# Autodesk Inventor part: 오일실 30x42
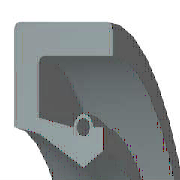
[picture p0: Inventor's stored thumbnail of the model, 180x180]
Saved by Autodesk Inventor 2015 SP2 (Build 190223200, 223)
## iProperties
IsCustomPart: 0
Company: 한국ATC센터
Created: 2009-02
Part Number: 오일실 30x42
Material: 고무
Description: 오일-실
Document SubType Name: Modeling
Standard: KS B 2804
Designer: KYOUNG IL JANG
Standards Organization: KS
Language: ko-KR
Size Designation: S - 30 42 8
Categories: <MemberInstance><Categories><Category DisplayName="샤프트 부품" InternalName="7f7aeb1f-a693-4053-b835-cee3144e0d98" Mnemonic="SHFT"><Category DisplayName="실링" Intern
Density: 0.93 g/cm^3
Appearance: 고무 - 검은색 - 버전 1.1
Author: KYOUNG IL JANG
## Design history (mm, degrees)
revolve "본체" stored, may be unused: angle "d17" = 90 deg
revolve "스프링1" stored, may be unused: angle "d18" = 90 deg
body "Solid1"
sketch "스케치1"
  geometry: L1 (0, 21)-(8, 21); L2 (8, 21)-(8, 19.75); L3 (8, 19.75)-(1.75, 19.75); L4 (0, 21)-(0, 17.1); L5 (0, 17.1)-(1.75, 16.75); L6 (1.75, 16.75)-(4.9, 15); L7 (4.9, 15)-(0, 15); L8 (6.3, 15.875)-(6.3, 17.1); L9 (0, 0)-(9.586, 0) reference; L10 (4.9, 15)-(6.3, 15.875); L11 (0, 18)-(0, -3) reference; L12 (-1.917, 0)-(11.503, 0) reference; L13 (4.2, 17.1)-(1.75, 17.59); L14 (1.75, 17.59)-(1.75, 19.75); L15 (6.3, 17.1)-(5.6, 17.1); C1 r 0.455 at (4.9, 17.1); A1 r 0.7 centre (4.9, 17.1) between (5.6, 17.1) and (4.2, 17.1)
  constraints: 26 end point, 5 horizontal alignment, 4 perpendicular, 2 centre point, 2 collinear, 2 horizontal, 2 parallel, 2 point on circle, 2 point on line, 2 vertical alignment, 1 coincident
  dimensions: "d0" = 42 diameter of L1 L9 (= SD2); "d1" = 31.75 diameter of L8.start L9 (= ABDM); "d2" = 1.25 distance of L1.end L2.end (computed from SD); "d3" = 0.91 diameter of C1 (= SPDI); "d4" = 1.4 diameter of A1 (= SPDA); "d5" = 30 diameter of L6.end L9 (= NND); "d6" = 33.5 diameter of L5.end L9 (= TKDM); "d7" = 34.2 diameter of L4.end L9 (= HLDM); "d8" = 4.9 distance from line of C1.centre L4 (= SPDST); "d9" = 6.3 distance between parallel lines of L8 L4 (= SDI); "d10" = 8 distance between parallel lines of L2 L4 (= SWDT); "d12" = 1.75 distance between parallel lines of L14 L4 (= SD)
fillet "모깎기1" dims "d11" = 0.4 (= RR)
other parameters: "SD2" = 42 [user parameter; used in 1 equation term], "SWDT" = 8 [user parameter; used in 1 equation term], "RR" = 0.4 [user parameter; used in 1 equation term], "SD" = 1.75 [user parameter; used in 2 equation terms], "NND" = 30 [user parameter; used in 1 equation term], "SPDA" = 1.4 [user parameter; used in 1 equation term], "SPDI" = 0.91 [user parameter; used in 1 equation term], "TKDM" = 33.5 [user parameter; used in 1 equation term], "HLDM" = 34.2 [user parameter; used in 1 equation term], "ABDM" = 31.75 [user parameter; used in 1 equation term], "SDI" = 6.3 [user parameter; used in 1 equation term], "SPDST" = 4.9 [user parameter; used in 1 equation term], "d13" = 0, "d14" = 0, "d15" = 0, "LAB" = 0.35 [user parameter]
